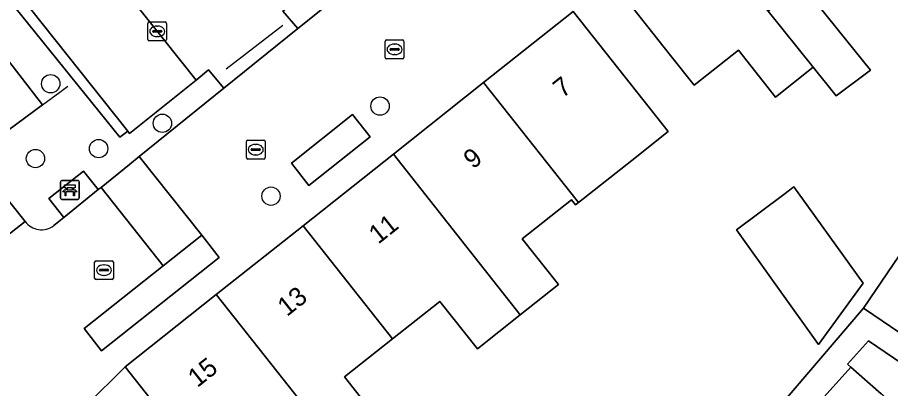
# Model space of a CAD drawing. Extents: x 161881 to 162523, y 381678 to 382381.
# Drawn here: x 162115.53 to 162162.08, y 382087.64 to 382107.41 of the extents above; entities that cross this region are included whole.
import ezdxf

# ---------------------------------------------------------------- set-up
doc = ezdxf.new("R2010")
doc.units = 0
for name, color, linetype in [('IMGEO_Bank', 7, 'Continuous'), ('IMGEO_Boom', 7, 'Continuous'), ('IMGEO_Erf', 7, 'Continuous'), ('IMGEO_Groenvoorziening', 7, 'Continuous'), ('IMGEO_Hek', 7, 'Continuous'), ('IMGEO_Kolk', 7, 'Continuous'), ('IMGEO_Pand', 7, 'Continuous'), ('IMGEO_Pand_nummerreeks', 7, 'Continuous'), ('IMGEO_Parkeervlak_open', 7, 'Continuous'), ('IMGEO_Rijbaan_lokaal_open', 7, 'Continuous'), ('IMGEO_Voetpad_open', 7, 'Continuous'), ('IMGEO_Woonerf_open', 7, 'Continuous')]:
    doc.layers.add(name, color=color, linetype=linetype)

msp = doc.modelspace()

# ---------------------------------------------------------------- linework, layer by layer
at = {"layer": 'IMGEO_Bank'}
for p, q in [((162117.824, 382097.792), (162117.824, 382098.633)), ((162117.824, 382098.633), (162117.824, 382097.792)), ((162117.899, 382098.717), (162118.74, 382098.717)), ((162118.74, 382098.717), (162117.899, 382098.717)), ((162118.824, 382098.642), (162118.824, 382097.801)), ((162118.824, 382097.801), (162118.824, 382098.642)), ((162118.521, 382098.115), (162118.128, 382098.115)), ((162118.133, 382098.223), (162118.133, 382098.329)), ((162118.177, 382098.329), (162118.177, 382098.223)), ((162118.465, 382098.335), (162118.183, 382098.335)), ((162118.183, 382098.217), (162118.465, 382098.217)), ((162118.471, 382098.223), (162118.471, 382098.329)), ((162118.515, 382098.329), (162118.515, 382098.223)), ((162118.749, 382097.717), (162117.908, 382097.717)), ((162117.908, 382097.717), (162118.749, 382097.717))]:
    msp.add_line(p, q, dxfattribs=at)
for points in [[(162118.071, 382098.115), (162117.929, 382098.115), (162118.041, 382098.217), (162118.127, 382098.217)], [(162118.127, 382098.335), (162118.041, 382098.335), (162118.041, 382098.496), (162118.604, 382098.496), (162118.604, 382098.335), (162118.521, 382098.335)], [(162118.121, 382098.108), (162118.121, 382097.901), (162118.078, 382097.901), (162118.078, 382098.108)], [(162118.521, 382098.217), (162118.604, 382098.217), (162118.716, 382098.115), (162118.577, 382098.115)], [(162118.571, 382098.108), (162118.571, 382097.901), (162118.527, 382097.901), (162118.527, 382098.108)]]:
    msp.add_lwpolyline(points, dxfattribs=at)
for centre, radius, start, end in [((162117.902, 382098.639), 0.0779, 92.4484, 184.2845), ((162117.902, 382098.639), 0.0779, 92.4484, 184.2845), ((162118.746, 382098.639), 0.0779, 2.4484, 94.2845), ((162118.746, 382098.639), 0.0779, 2.4484, 94.2845), ((162118.071, 382098.108), 0.00671, 2.8957, 87.1043), ((162118.128, 382098.108), 0.00671, 92.8957, 177.1043), ((162118.126, 382098.328), 0.00671, 2.8957, 87.1043), ((162118.126, 382098.224), 0.00671, 272.8957, 357.1043), ((162118.183, 382098.328), 0.00671, 92.8957, 177.1043), ((162118.183, 382098.224), 0.00671, 182.8957, 267.1043), ((162118.465, 382098.328), 0.00671, 2.8957, 87.1043), ((162118.465, 382098.224), 0.00671, 272.8957, 357.1043), ((162118.522, 382098.328), 0.00671, 92.8957, 177.1043), ((162118.522, 382098.224), 0.00671, 182.8957, 267.1043), ((162118.52, 382098.108), 0.00671, 2.8957, 87.1043), ((162118.577, 382098.108), 0.00671, 92.8957, 177.1043), ((162117.902, 382097.795), 0.0779, 182.4484, 274.2845), ((162117.902, 382097.795), 0.0779, 182.4484, 274.2845), ((162118.746, 382097.795), 0.0779, 272.4484, 4.2845), ((162118.746, 382097.795), 0.0779, 272.4484, 4.2845)]:
    msp.add_arc(centre, radius, start, end, dxfattribs=at)
at = {"layer": 'IMGEO_Boom'}
for centre in [(162117.307, 382103.877), (162134.861, 382102.686), (162123.261, 382101.77), (162119.859, 382100.419), (162116.494, 382099.892), (162129.049, 382097.887)]:
    msp.add_circle(centre, 0.489, dxfattribs=at)
at = {"layer": 'IMGEO_Erf'}
for points in [[(162157.375, 382109.104), (162161.012, 382104.595), (162159.185, 382103.227), (162157.952, 382104.755), (162155.951, 382103.169), (162153.966, 382105.673), (162151.606, 382103.803), (162150.352, 382105.385), (162147.247, 382109.304)], [(162145.159, 382107.718), (162148.264, 382103.799), (162150.222, 382101.329), (162148.282, 382099.792), (162145.441, 382097.542), (162145.285, 382097.418), (162145.072, 382097.687), (162142.444, 382095.605), (162144.371, 382093.174), (162142.34, 382091.565), (162140.05, 382089.751), (162138.044, 382092.283), (162135.52, 382090.284), (162132.966, 382088.26), (162135.001, 382085.691)], [(162153.143, 382083.147), (162160.636, 382091.92), (162164.091, 382097.012)], [(162168.507, 382085.007), (162160.894, 382090.174), (162159.781, 382088.94), (162159.965, 382088.777), (162161.576, 382087.357)], [(162124.475, 382084.752), (162121.273, 382088.793), (162119.199, 382086.737)]]:
    msp.add_lwpolyline(points, dxfattribs=at)
msp.add_lwpolyline([(162153.865, 382096.09), (162156.38, 382097.98), (162156.686, 382098.21), (162156.871, 382098.349), (162156.928, 382098.392), (162157.703, 382097.308), (162160.609, 382093.249), (162158.23, 382089.991)], close=True, dxfattribs=at)
at = {"layer": 'IMGEO_Groenvoorziening'}
for points in [[(162132.956, 382116.323), (162132.796, 382116.521), (162129.478, 382119.862), (162126.569, 382122.976), (162126.247, 382123.32), (162123.474, 382126.921), (162120.058, 382131.359), (162116.536, 382127.884), (162116.309, 382128.058), (162106.899, 382118.44), (162107.907, 382117.216), (162108.469, 382117.615), (162112.012, 382120.419), (162117.385, 382124.671), (162120.906, 382127.458), (162133.886, 382111.152), (162130.444, 382108.362), (162129.686, 382107.748), (162130.473, 382106.822), (162136.002, 382111.248), (162136.61, 382110.616), (162137.218, 382111.056)], [(162131.069, 382098.463), (162134.337, 382101.051), (162133.403, 382102.23), (162130.136, 382099.641)], [(162123.302, 382094.176), (162119.083, 382090.833), (162120.022, 382089.647), (162126.294, 382094.616), (162125.355, 382095.802)]]:
    msp.add_lwpolyline(points, close=True, dxfattribs=at)
msp.add_lwpolyline([(162117.466, 382096.317), (162118.006, 382096.754), (162117.215, 382097.756), (162119.049, 382099.221), (162119.843, 382098.237), (162119.991, 382098.357), (162121.505, 382099.58), (162122.028, 382100.003), (162126.539, 382103.647), (162125.726, 382104.611), (162125.058, 382104.075), (162121.513, 382101.233), (162121.424, 382101.345), (162121, 382101.024), (162107.907, 382117.216), (162107.71, 382117.031), (162107.794, 382116.925), (162106.628, 382115.719), (162114.38, 382105.944), (162116.87, 382102.749), (162113.15, 382100.011), (162115.951, 382096.535)], dxfattribs=at)
msp.add_arc((162116.815, 382097.166), 1.07, 216.1449, 307.4785, dxfattribs=at)
at = {"layer": 'IMGEO_Hek'}
for points in [[(162126.654, 382104.673), (162129.678, 382107.004)], [(162117.799, 382103.435), (162118.224, 382103.748)], [(162116.87, 382102.749), (162117.799, 382103.435)]]:
    msp.add_lwpolyline(points, dxfattribs=at)
at = {"layer": 'IMGEO_Kolk'}
for p, q in [((162122.484, 382106.243), (162122.484, 382107.095)), ((162122.559, 382107.169), (162123.411, 382107.169)), ((162122.972, 382106.949), (162122.997, 382106.949)), ((162123.485, 382107.095), (162123.485, 382106.243)), ((162122.743, 382106.663), (162122.743, 382106.675)), ((162123.181, 382106.626), (162122.783, 382106.626)), ((162122.786, 382106.712), (162123.184, 382106.712)), ((162123.227, 382106.675), (162123.227, 382106.663)), ((162123.411, 382106.169), (162122.559, 382106.169)), ((162122.995, 382106.389), (162122.97, 382106.389)), ((162135.137, 382105.282), (162135.137, 382106.134)), ((162135.212, 382106.208), (162136.064, 382106.208)), ((162136.138, 382106.134), (162136.138, 382105.282)), ((162135.396, 382105.702), (162135.396, 382105.714)), ((162135.834, 382105.665), (162135.436, 382105.665)), ((162135.439, 382105.751), (162135.837, 382105.751)), ((162135.625, 382105.988), (162135.65, 382105.988)), ((162135.88, 382105.714), (162135.88, 382105.702)), ((162136.064, 382105.208), (162135.212, 382105.208)), ((162135.648, 382105.428), (162135.623, 382105.428)), ((162127.737, 382099.941), (162127.737, 382100.793)), ((162127.812, 382100.867), (162128.664, 382100.867)), ((162128.225, 382100.647), (162128.25, 382100.647)), ((162128.738, 382100.793), (162128.738, 382099.941)), ((162127.996, 382100.361), (162127.996, 382100.373)), ((162128.434, 382100.324), (162128.036, 382100.324)), ((162128.039, 382100.41), (162128.437, 382100.41)), ((162128.248, 382100.087), (162128.223, 382100.087)), ((162128.48, 382100.373), (162128.48, 382100.361)), ((162128.664, 382099.867), (162127.812, 382099.867)), ((162119.648, 382093.522), (162119.648, 382094.374)), ((162119.723, 382094.448), (162120.575, 382094.448)), ((162120.649, 382094.374), (162120.649, 382093.522)), ((162119.907, 382093.942), (162119.907, 382093.954)), ((162120.345, 382093.905), (162119.947, 382093.905)), ((162119.95, 382093.991), (162120.348, 382093.991)), ((162120.136, 382094.228), (162120.161, 382094.228)), ((162120.391, 382093.954), (162120.391, 382093.942)), ((162120.575, 382093.448), (162119.723, 382093.448)), ((162120.159, 382093.668), (162120.134, 382093.668))]:
    msp.add_line(p, q, dxfattribs=at)
for points in [[(162122.484, 382106.243), (162122.484, 382107.095)], [(162122.559, 382107.169), (162123.411, 382107.169)], [(162123.485, 382107.095), (162123.485, 382106.243)], [(162123.411, 382106.169), (162122.559, 382106.169)], [(162135.137, 382105.282), (162135.137, 382106.134)], [(162135.212, 382106.208), (162136.064, 382106.208)], [(162136.138, 382106.134), (162136.138, 382105.282)], [(162136.064, 382105.208), (162135.212, 382105.208)], [(162127.737, 382099.941), (162127.737, 382100.793)], [(162127.812, 382100.867), (162128.664, 382100.867)], [(162128.738, 382100.793), (162128.738, 382099.941)], [(162128.664, 382099.867), (162127.812, 382099.867)], [(162119.648, 382093.522), (162119.648, 382094.374)], [(162119.723, 382094.448), (162120.575, 382094.448)], [(162120.649, 382094.374), (162120.649, 382093.522)], [(162120.575, 382093.448), (162119.723, 382093.448)]]:
    msp.add_lwpolyline(points, dxfattribs=at)
for centre, radius, start, end in [((162122.561, 382107.093), 0.0765, 91.552, 178.448), ((162122.561, 382107.093), 0.0765, 91.552, 178.448), ((162123.409, 382107.093), 0.0765, 1.552, 88.448), ((162123.409, 382107.093), 0.0765, 1.552, 88.448), ((162122.783, 382106.672), 0.0403, 85.8775, 175.7526), ((162122.78, 382106.662), 0.0366, 178.938, 274.7102), ((162123.184, 382106.669), 0.043, 264.8664, 352.4533), ((162123.188, 382106.674), 0.0386, 1.7309, 96.639), ((162122.561, 382106.245), 0.0765, 181.552, 268.448), ((162122.561, 382106.245), 0.0765, 181.552, 268.448), ((162123.409, 382106.245), 0.0765, 271.552, 358.448), ((162123.409, 382106.245), 0.0765, 271.552, 358.448), ((162135.214, 382106.132), 0.0765, 91.552, 178.448), ((162135.214, 382106.132), 0.0765, 91.552, 178.448), ((162136.062, 382106.132), 0.0765, 1.552, 88.448), ((162136.062, 382106.132), 0.0765, 1.552, 88.448), ((162135.436, 382105.711), 0.0403, 85.8775, 175.7526), ((162135.433, 382105.701), 0.0366, 178.938, 274.7102), ((162135.837, 382105.708), 0.043, 264.8664, 352.4533), ((162135.841, 382105.713), 0.0386, 1.7309, 96.639), ((162135.214, 382105.284), 0.0765, 181.552, 268.448), ((162135.214, 382105.284), 0.0765, 181.552, 268.448), ((162136.062, 382105.284), 0.0765, 271.552, 358.448), ((162136.062, 382105.284), 0.0765, 271.552, 358.448), ((162127.814, 382100.791), 0.0765, 91.552, 178.448), ((162127.814, 382100.791), 0.0765, 91.552, 178.448), ((162128.441, 382100.372), 0.0386, 1.7309, 96.639), ((162128.662, 382100.791), 0.0765, 1.552, 88.448), ((162128.662, 382100.791), 0.0765, 1.552, 88.448), ((162128.036, 382100.37), 0.0403, 85.8775, 175.7526), ((162128.033, 382100.36), 0.0366, 178.938, 274.7102), ((162128.437, 382100.367), 0.043, 264.8664, 352.4533), ((162127.814, 382099.943), 0.0765, 181.552, 268.448), ((162127.814, 382099.943), 0.0765, 181.552, 268.448), ((162128.662, 382099.943), 0.0765, 271.552, 358.448), ((162128.662, 382099.943), 0.0765, 271.552, 358.448), ((162119.725, 382094.372), 0.0765, 91.552, 178.448), ((162119.725, 382094.372), 0.0765, 91.552, 178.448), ((162120.573, 382094.372), 0.0765, 1.552, 88.448), ((162120.573, 382094.372), 0.0765, 1.552, 88.448), ((162119.947, 382093.951), 0.0403, 85.8775, 175.7526), ((162119.944, 382093.941), 0.0366, 178.938, 274.7102), ((162120.348, 382093.948), 0.043, 264.8664, 352.4533), ((162120.352, 382093.953), 0.0386, 1.7309, 96.639), ((162119.725, 382093.524), 0.0765, 181.552, 268.448), ((162119.725, 382093.524), 0.0765, 181.552, 268.448), ((162120.573, 382093.524), 0.0765, 271.552, 358.448), ((162120.573, 382093.524), 0.0765, 271.552, 358.448)]:
    msp.add_arc(centre, radius, start, end, dxfattribs=at)
for centre, major_axis, ratio, start_param, end_param in [((162122.971, 382106.669), (-0.387, 0.002), 0.722429, 4.712389, 7.853982), ((162122.996, 382106.669), (-0.39, 0.002), 0.717154, 1.570796, 4.712389), ((162135.624, 382105.708), (-0.387, 0.002), 0.722429, 4.712389, 7.853982), ((162135.649, 382105.708), (-0.39, 0.002), 0.717154, 1.570796, 4.712389), ((162128.224, 382100.367), (-0.387, 0.002), 0.722429, 4.712389, 7.853982), ((162128.249, 382100.367), (-0.39, 0.002), 0.717154, 1.570796, 4.712389), ((162120.135, 382093.948), (-0.387, 0.002), 0.722429, 4.712389, 7.853982), ((162120.16, 382093.948), (-0.39, 0.002), 0.717154, 1.570796, 4.712389)]:
    msp.add_ellipse(centre, major_axis=major_axis, ratio=ratio, start_param=start_param, end_param=end_param, dxfattribs=at)
at = {"layer": 'IMGEO_Pand'}
for points in [[(162155.548, 382107.736), (162151.509, 382112.743), (162147.247, 382109.304), (162150.352, 382105.385), (162151.606, 382103.803), (162153.966, 382105.673), (162155.951, 382103.169), (162157.952, 382104.755)], [(162157.375, 382109.104), (162155.715, 382107.861), (162155.548, 382107.736), (162157.952, 382104.755), (162159.185, 382103.227), (162161.012, 382104.595)], [(162148.264, 382103.799), (162145.159, 382107.718), (162140.384, 382103.935), (162145.441, 382097.542), (162148.282, 382099.792), (162150.222, 382101.329)], [(162142.34, 382091.565), (162144.371, 382093.174), (162142.444, 382095.605), (162145.072, 382097.687), (162145.285, 382097.418), (162145.441, 382097.542), (162140.384, 382103.935), (162135.571, 382100.121)], [(162142.34, 382091.565), (162135.571, 382100.121), (162130.756, 382096.306), (162135.52, 382090.284), (162138.044, 382092.283), (162140.05, 382089.751)], [(162156.38, 382097.98), (162153.865, 382096.09), (162158.23, 382089.991), (162160.609, 382093.249), (162157.703, 382097.308), (162156.928, 382098.392), (162156.871, 382098.349), (162156.686, 382098.21)], [(162167.331, 382094.773), (162164.091, 382097.012), (162160.636, 382091.92), (162178.163, 382080.027), (162181.518, 382084.967)], [(162135.52, 382090.284), (162130.756, 382096.306), (162126.131, 382092.642), (162132.929, 382084.049), (162135.001, 382085.691), (162132.966, 382088.26)], [(162126.131, 382092.642), (162121.273, 382088.793), (162124.475, 382084.752), (162126.171, 382082.612), (162128.078, 382080.206), (162128.25, 382080.342), (162130.666, 382082.256), (162132.929, 382084.049)], [(162161.86, 382087.106), (162161.664, 382087.279), (162161.576, 382087.357), (162159.965, 382088.777), (162156.951, 382085.435), (162158.446, 382084.421), (162158.685, 382084.259), (162158.888, 382084.121), (162159.106, 382083.973)]]:
    msp.add_lwpolyline(points, close=True, dxfattribs=at)
at = {"layer": 'IMGEO_Parkeervlak_open'}
msp.add_lwpolyline([(162125.058, 382104.075), (162112.012, 382120.419), (162108.469, 382117.615), (162121.424, 382101.345), (162121.513, 382101.233)], close=True, dxfattribs=at)
at = {"layer": 'IMGEO_Rijbaan_lokaal_open'}
for points in [[(162117.385, 382124.671), (162112.012, 382120.419), (162125.058, 382104.075), (162125.726, 382104.611), (162126.539, 382103.647), (162130.473, 382106.822), (162129.686, 382107.748), (162130.444, 382108.362)], [(162125.355, 382095.802), (162122.028, 382100.003), (162121.505, 382099.58), (162119.991, 382098.357), (162123.302, 382094.176)]]:
    msp.add_lwpolyline(points, close=True, dxfattribs=at)
msp.add_lwpolyline([(162113.69, 382094.776), (162115.951, 382096.535), (162113.15, 382100.011)], dxfattribs=at)
at = {"layer": 'IMGEO_Voetpad_open'}
for points in [[(162121.424, 382101.345), (162108.469, 382117.615), (162107.907, 382117.216), (162121, 382101.024)], [(162111.653, 382098.909), (162113.15, 382100.011), (162116.87, 382102.749), (162114.38, 382105.944), (162113.565, 382105.319), (162109.226, 382101.989)], [(162119.843, 382098.237), (162119.049, 382099.221), (162117.215, 382097.756), (162118.006, 382096.754)]]:
    msp.add_lwpolyline(points, close=True, dxfattribs=at)
for points in [[(162178.163, 382080.027), (162160.636, 382091.92), (162153.143, 382083.147)], [(162156.951, 382085.435), (162159.965, 382088.777), (162159.781, 382088.94), (162160.894, 382090.174), (162168.507, 382085.007)]]:
    msp.add_lwpolyline(points, dxfattribs=at)
at = {"layer": 'IMGEO_Woonerf_open'}
for points in [[(162136.002, 382111.248), (162130.473, 382106.822), (162126.539, 382103.647), (162122.028, 382100.003), (162125.355, 382095.802), (162126.294, 382094.616), (162120.022, 382089.647), (162119.083, 382090.833), (162123.302, 382094.176), (162119.991, 382098.357), (162119.843, 382098.237), (162118.006, 382096.754), (162117.466, 382096.317)], [(162119.199, 382086.737), (162121.273, 382088.793), (162126.131, 382092.642), (162130.756, 382096.306), (162135.571, 382100.121), (162140.384, 382103.935), (162145.159, 382107.718)], [(162115.951, 382096.535), (162113.69, 382094.776), (162112.431, 382093.718), (162106.745, 382088.664), (162102.969, 382085.099)]]:
    msp.add_lwpolyline(points, dxfattribs=at)
msp.add_lwpolyline([(162130.136, 382099.641), (162133.403, 382102.23), (162134.337, 382101.051), (162131.069, 382098.463)], close=True, dxfattribs=at)
msp.add_arc((162116.815, 382097.166), 1.07, 216.1449, 307.4785, dxfattribs=at)

# ---------------------------------------------------------------- texts
at = {"layer": 'IMGEO_Pand_nummerreeks'}
for s, rotation, p in [('7', 38.3882, (162144.591, 382103.083)), ('9', 38.39, (162139.814, 382099.298)), ('11', 38.39, (162134.766, 382095.298)), ('13', 38.39, (162129.9, 382091.442)), ('15', 38.3882, (162125.123, 382087.658))]:
    msp.add_text(s, height=1, rotation=rotation, dxfattribs=at).set_placement(p)

doc.saveas('drawing.dxf')
